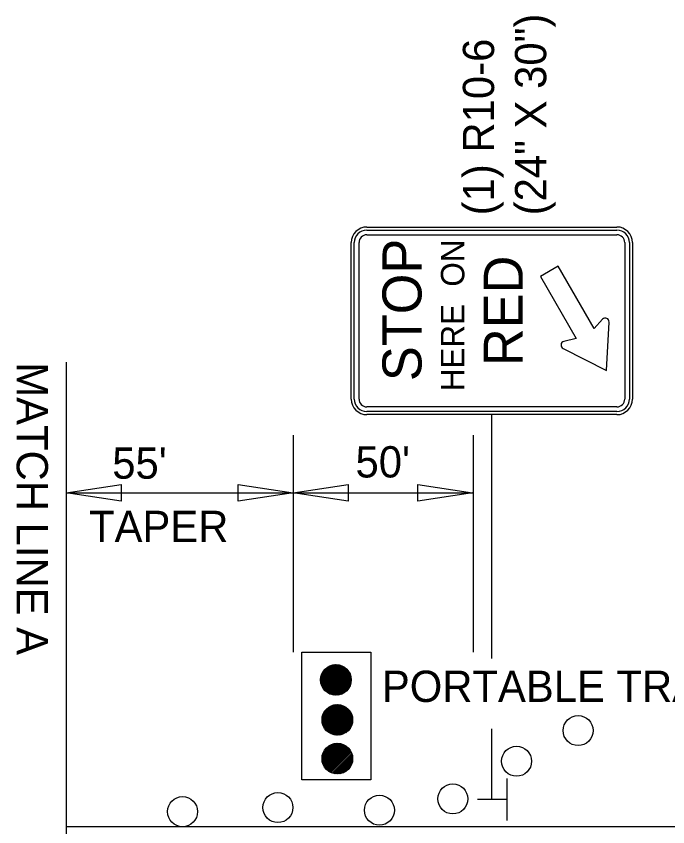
# Model space of a CAD drawing. Extents: x 1927831 to 1930787, y 596452 to 597699.
# Drawn here: x 1927831.5 to 1927956.5, y 597037.3 to 597192.8 of the extents above; entities that cross this region are included whole.
import ezdxf

# ---------------------------------------------------------------- set-up
doc = ezdxf.new("R2010")
doc.units = 0
for name, color, linetype in [('Default', 7, 'Continuous'), ('P_TC_Signs_Permanent', 7, 'Continuous'), ('R_Border', 7, 'Continuous')]:
    doc.layers.add(name, color=color, linetype=linetype)

msp = doc.modelspace()

# ---------------------------------------------------------------- linework, layer by layer
at = {"layer": 'Default'}
for p, q in [((1927841.07, 597126.4), (1927841.07, 597001.76)), ((1927884.63, 597112.39), (1927884.63, 597070.81)), ((1927919.2, 597112.39), (1927919.2, 597070.81)), ((1927841.07, 597101.35), (1927851.62, 597102.93)), ((1927851.62, 597102.93), (1927851.62, 597099.77)), ((1927874.09, 597099.77), (1927874.09, 597102.93)), ((1927874.09, 597102.93), (1927884.63, 597101.35)), ((1927884.63, 597101.35), (1927895.17, 597102.93)), ((1927895.17, 597102.93), (1927895.17, 597099.77)), ((1927908.54, 597099.77), (1927908.54, 597102.93)), ((1927908.54, 597102.93), (1927919.08, 597101.35)), ((1927851.62, 597099.77), (1927841.07, 597101.35)), ((1927841.07, 597101.35), (1927884.63, 597101.35)), ((1927884.63, 597101.35), (1927874.09, 597099.77)), ((1927884.63, 597101.35), (1927919.08, 597101.35)), ((1927895.17, 597099.77), (1927884.63, 597101.35)), ((1927919.08, 597101.35), (1927908.54, 597099.77)), ((1927889.9, 597065.5), (1927892.8, 597068.4)), ((1927889.91, 597065.32), (1927892.98, 597068.39)), ((1927889.91, 597065.69), (1927892.61, 597068.39)), ((1927889.92, 597065.15), (1927893.15, 597068.38)), ((1927889.94, 597064.99), (1927893.31, 597068.36)), ((1927889.94, 597065.89), (1927892.41, 597068.36)), ((1927889.97, 597064.84), (1927893.46, 597068.33)), ((1927889.98, 597066.12), (1927892.19, 597068.32)), ((1927890, 597064.69), (1927893.61, 597068.3)), ((1927890.04, 597064.55), (1927893.75, 597068.26)), ((1927890.05, 597066.37), (1927891.93, 597068.25)), ((1927890.09, 597064.42), (1927893.88, 597068.21)), ((1927890.14, 597064.29), (1927894.01, 597068.16)), ((1927890.16, 597066.66), (1927891.64, 597068.14)), ((1927890.2, 597064.17), (1927894.13, 597068.1)), ((1927890.26, 597064.05), (1927894.25, 597068.04)), ((1927890.33, 597063.93), (1927894.37, 597067.97)), ((1927890.38, 597067.06), (1927891.24, 597067.92)), ((1927890.4, 597063.82), (1927894.48, 597067.9)), ((1927890.47, 597063.72), (1927894.58, 597067.83)), ((1927890.55, 597063.61), (1927894.69, 597067.75)), ((1927890.63, 597063.52), (1927894.79, 597067.67)), ((1927890.72, 597063.42), (1927894.88, 597067.58)), ((1927890.81, 597063.33), (1927894.97, 597067.49)), ((1927890.91, 597063.24), (1927895.06, 597067.4)), ((1927891, 597063.16), (1927895.14, 597067.3)), ((1927891.11, 597063.08), (1927895.22, 597067.19)), ((1927891.21, 597063.01), (1927895.29, 597067.09)), ((1927891.32, 597062.94), (1927895.36, 597066.98)), ((1927891.44, 597062.87), (1927895.43, 597066.86)), ((1927891.56, 597062.81), (1927895.49, 597066.74)), ((1927891.68, 597062.75), (1927895.55, 597066.62)), ((1927891.81, 597062.7), (1927895.6, 597066.49)), ((1927891.94, 597062.66), (1927895.65, 597066.36)), ((1927892.08, 597062.61), (1927895.69, 597066.22)), ((1927892.23, 597062.58), (1927895.72, 597066.07)), ((1927892.38, 597062.55), (1927895.75, 597065.92)), ((1927892.54, 597062.53), (1927895.77, 597065.76)), ((1927892.71, 597062.52), (1927895.78, 597065.59)), ((1927892.89, 597062.51), (1927895.79, 597065.41)), ((1927893.08, 597062.52), (1927895.78, 597065.22)), ((1927893.28, 597062.55), (1927895.75, 597065.02)), ((1927893.51, 597062.59), (1927895.71, 597064.79)), ((1927893.76, 597062.66), (1927895.64, 597064.54)), ((1927894.05, 597062.77), (1927895.53, 597064.25)), ((1927894.45, 597062.99), (1927895.31, 597063.85)), ((1927890.17, 597057.84), (1927893.07, 597060.74)), ((1927890.18, 597057.66), (1927893.25, 597060.74)), ((1927890.18, 597058.03), (1927892.88, 597060.73)), ((1927890.19, 597057.49), (1927893.42, 597060.72)), ((1927890.21, 597058.23), (1927892.68, 597060.71)), ((1927890.21, 597057.33), (1927893.58, 597060.7)), ((1927890.24, 597057.18), (1927893.73, 597060.67)), ((1927890.25, 597058.46), (1927892.45, 597060.66)), ((1927890.27, 597057.03), (1927893.88, 597060.64)), ((1927890.31, 597056.9), (1927894.02, 597060.6)), ((1927890.32, 597058.71), (1927892.2, 597060.59)), ((1927890.36, 597056.76), (1927894.15, 597060.55)), ((1927890.41, 597056.63), (1927894.28, 597060.5)), ((1927890.43, 597059), (1927891.91, 597060.48)), ((1927890.47, 597056.51), (1927894.4, 597060.44)), ((1927890.53, 597056.39), (1927894.52, 597060.38)), ((1927890.6, 597056.27), (1927894.64, 597060.31)), ((1927890.65, 597059.4), (1927891.51, 597060.26)), ((1927890.67, 597056.16), (1927894.75, 597060.24)), ((1927890.74, 597056.06), (1927894.85, 597060.17)), ((1927890.82, 597055.95), (1927894.96, 597060.09)), ((1927890.9, 597055.86), (1927895.05, 597060.01)), ((1927890.99, 597055.76), (1927895.15, 597059.92)), ((1927891.08, 597055.67), (1927895.24, 597059.83)), ((1927891.17, 597055.58), (1927895.33, 597059.74)), ((1927891.27, 597055.5), (1927895.41, 597059.64)), ((1927891.38, 597055.42), (1927895.49, 597059.54)), ((1927891.48, 597055.35), (1927895.56, 597059.43)), ((1927891.59, 597055.28), (1927895.63, 597059.32)), ((1927891.71, 597055.21), (1927895.7, 597059.2)), ((1927891.83, 597055.15), (1927895.76, 597059.08)), ((1927891.95, 597055.09), (1927895.82, 597058.96)), ((1927892.08, 597055.04), (1927895.87, 597058.83)), ((1927892.21, 597055), (1927895.91, 597058.7)), ((1927892.35, 597054.96), (1927895.96, 597058.56)), ((1927892.5, 597054.92), (1927895.99, 597058.41)), ((1927892.65, 597054.89), (1927896.02, 597058.26)), ((1927892.81, 597054.87), (1927896.04, 597058.1)), ((1927892.98, 597054.86), (1927896.05, 597057.93)), ((1927893.16, 597054.86), (1927896.06, 597057.75)), ((1927893.35, 597054.86), (1927896.05, 597057.56)), ((1927893.55, 597054.89), (1927896.02, 597057.36)), ((1927893.78, 597054.93), (1927895.98, 597057.13)), ((1927894.03, 597055), (1927895.91, 597056.88)), ((1927894.32, 597055.11), (1927895.8, 597056.59)), ((1927894.72, 597055.33), (1927895.58, 597056.19)), ((1927890.17, 597050.32), (1927893.15, 597053.3)), ((1927890.18, 597050.5), (1927892.97, 597053.3)), ((1927890.18, 597050.15), (1927893.33, 597053.29)), ((1927890.19, 597050.7), (1927892.77, 597053.28)), ((1927890.2, 597049.98), (1927893.49, 597053.28)), ((1927890.22, 597049.83), (1927893.65, 597053.25)), ((1927890.23, 597050.92), (1927892.56, 597053.25)), ((1927890.25, 597049.68), (1927893.8, 597053.22)), ((1927890.28, 597051.15), (1927892.32, 597053.19)), ((1927890.29, 597049.53), (1927893.94, 597053.18)), ((1927890.33, 597049.4), (1927894.08, 597053.14)), ((1927890.37, 597051.42), (1927892.05, 597053.1)), ((1927890.38, 597049.26), (1927894.21, 597053.09)), ((1927890.44, 597049.14), (1927894.33, 597053.03)), ((1927890.5, 597049.02), (1927894.46, 597052.98)), ((1927890.53, 597051.76), (1927891.71, 597052.94)), ((1927890.56, 597048.9), (1927894.57, 597052.91)), ((1927890.63, 597048.79), (1927894.69, 597052.84)), ((1927890.7, 597048.68), (1927894.8, 597052.77)), ((1927890.78, 597048.57), (1927894.9, 597052.7)), ((1927890.86, 597048.47), (1927895, 597052.62)), ((1927890.94, 597048.37), (1927895.1, 597052.53)), ((1927891.03, 597048.28), (1927895.19, 597052.44)), ((1927891.12, 597048.19), (1927895.28, 597052.35)), ((1927891.22, 597048.11), (1927895.36, 597052.25)), ((1927891.32, 597048.03), (1927895.44, 597052.15)), ((1927891.42, 597047.95), (1927895.52, 597052.05)), ((1927891.53, 597047.88), (1927895.59, 597051.94)), ((1927891.64, 597047.81), (1927895.66, 597051.83)), ((1927891.76, 597047.75), (1927895.73, 597051.71)), ((1927891.88, 597047.69), (1927895.78, 597051.59)), ((1927892.14, 597047.58), (1927895.89, 597051.33)), ((1927892.27, 597047.54), (1927895.93, 597051.2)), ((1927892.42, 597047.5), (1927895.97, 597051.05)), ((1927892.57, 597047.47), (1927896, 597050.91)), ((1927892.72, 597047.44), (1927896.03, 597050.75)), ((1927892.89, 597047.42), (1927896.05, 597050.59)), ((1927893.06, 597047.42), (1927896.06, 597050.41)), ((1927893.24, 597047.42), (1927896.05, 597050.23)), ((1927893.44, 597047.43), (1927896.04, 597050.04)), ((1927893.65, 597047.46), (1927896.01, 597049.82)), ((1927893.88, 597047.52), (1927895.95, 597049.59)), ((1927894.15, 597047.6), (1927895.87, 597049.32)), ((1927894.48, 597047.75), (1927895.72, 597048.99)), ((1927895.05, 597048.14), (1927895.33, 597048.42)), ((1927925.62, 597046.52), (1927925.62, 597038.52)), ((1927925.51, 597042.54), (1927920.04, 597042.54)), ((1927841.07, 597037.34), (1928485.68, 597037.29))]:
    msp.add_line(p, q, dxfattribs=at)
msp.add_lwpolyline([(1927886.27, 597070.81), (1927899.56, 597070.81), (1927899.56, 597046.27), (1927886.27, 597046.27)], close=True, dxfattribs=at)
for centre, radius in [((1927892.84, 597065.46), 2.94), ((1927893.11, 597057.8), 2.94), ((1927939.33, 597055.74), 2.88), ((1927893.11, 597050.36), 2.94), ((1927927.51, 597049.86), 2.88), ((1927915.28, 597042.64), 2.88), ((1927881.71, 597040.97), 2.88), ((1927863.4, 597040.19), 2.88), ((1927901.19, 597040.47), 2.88)]:
    msp.add_circle(centre, radius, dxfattribs=at)
at = {"layer": 'P_TC_Signs_Permanent'}
for p, q in [((1927898.77, 597152.35), (1927946.77, 597152.35)), ((1927898.77, 597151.75), (1927946.77, 597151.75)), ((1927898.77, 597150.85), (1927946.77, 597150.85)), ((1927895.77, 597119.35), (1927895.77, 597149.35)), ((1927896.37, 597119.35), (1927896.37, 597149.35)), ((1927897.27, 597119.35), (1927897.27, 597149.35)), ((1927948.27, 597149.35), (1927948.27, 597119.35)), ((1927949.17, 597149.35), (1927949.17, 597119.35)), ((1927949.77, 597149.35), (1927949.77, 597119.35)), ((1927946.77, 597117.85), (1927898.77, 597117.85)), ((1927946.77, 597116.95), (1927898.77, 597116.95)), ((1927946.77, 597116.35), (1927898.77, 597116.35))]:
    msp.add_line(p, q, dxfattribs=at)
for points in [[(1927944.02, 597134.66), (1927942.38, 597132.91), (1927935.49, 597144.84), (1927932.08, 597142.87), (1927938.97, 597130.94), (1927936.6, 597130.4)], [(1927936.44, 597129.05), (1927944.76, 597124.85), (1927945.27, 597134.12)]]:
    msp.add_lwpolyline(points, dxfattribs=at)
for centre, radius, start, end in [((1927898.77, 597149.35), 3, 90, 180), ((1927946.77, 597149.35), 3, 360, 90), ((1927898.77, 597149.35), 2.4, 90, 180), ((1927898.77, 597149.35), 1.5, 90, 180), ((1927946.77, 597149.35), 2.4, 360, 90), ((1927946.77, 597149.35), 1.5, 360, 90), ((1927944.55, 597134.16), 0.72, 356.857, 136.6377), ((1927936.76, 597129.69), 0.72, 103.0349, 243.2286), ((1927898.77, 597119.35), 3, 180, 270), ((1927898.77, 597119.35), 2.4, 180, 270), ((1927898.77, 597119.35), 1.5, 180, 270), ((1927946.77, 597119.35), 3, 270, 360), ((1927946.77, 597119.35), 2.4, 270, 360), ((1927946.77, 597119.35), 1.5, 270, 360)]:
    msp.add_arc(centre, radius, start, end, dxfattribs=at)
at = {"layer": 'R_Border'}
for p, q in [((1927922.77, 597069.6), (1927922.77, 597116.35)), ((1927922.77, 597042.54), (1927922.77, 597056.07))]:
    msp.add_line(p, q, dxfattribs=at)

# ---------------------------------------------------------------- texts
at = {"layer": 'Default'}
for s, rotation, p in [('MATCH LINE A', 270, (1927831.56, 597126.4)), ("50'", 360, (1927896.6, 597104.3)), ("  55' ", 360, (1927845.45, 597104.06)), ('TAPER', 360, (1927845.45, 597091.92)), ('PORTABLE TRAFFIC SIGNAL SYSTEM', 360, (1927901.66, 597061.24))]:
    msp.add_text(s, height=6, rotation=rotation, dxfattribs=at).set_placement(p)
at = {"layer": 'P_TC_Signs_Permanent'}
for s, height, p in [('STOP', 7.5, (1927909.27, 597122.79)), ('HERE  ON', 4.5, (1927917.49, 597120.85)), ('RED', 7.5, (1927928.71, 597125.68))]:
    msp.add_text(s, height=height, rotation=90, dxfattribs=at).set_placement(p)
at = {"layer": 'R_Border'}
for s, height, p in [('(24" X 30")', 5.9996, (1927933.21, 597154.59)), ('(1) R10-6', 6, (1927923.2, 597154.59))]:
    msp.add_text(s, height=height, rotation=90, dxfattribs=at).set_placement(p)

doc.saveas('drawing.dxf')
